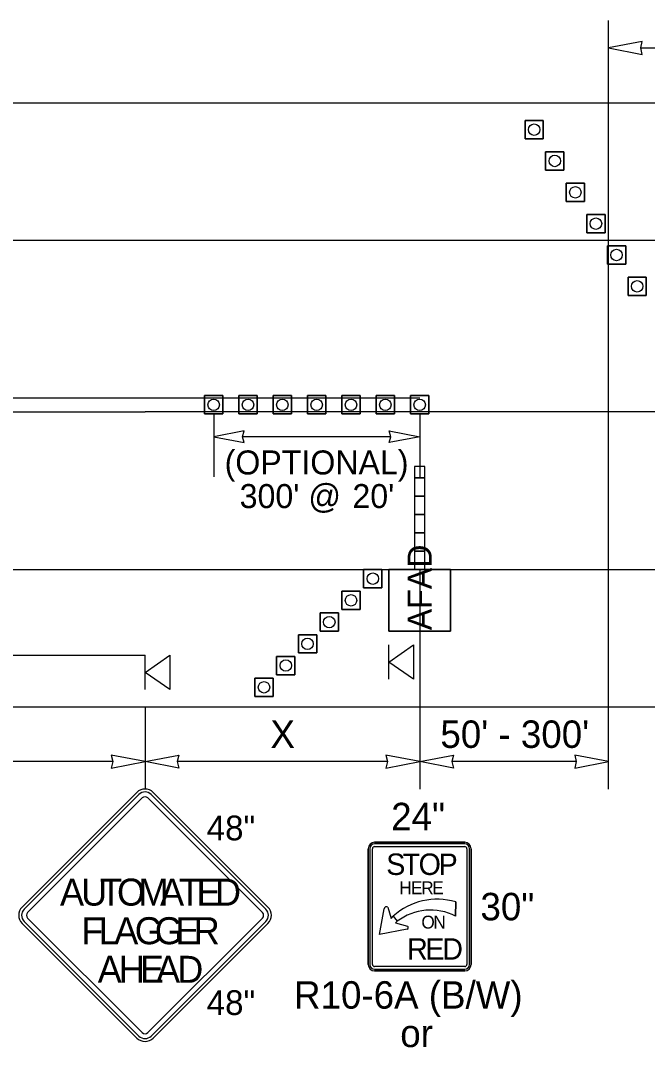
# Model space of a CAD drawing. Extents: x 99999.1 to 100095.7, y 99995 to 100010.7.
# Drawn here: x 100003.114 to 100004.94, y 100004.739 to 100007.732 of the extents above; entities that cross this region are included whole.
import ezdxf

# ---------------------------------------------------------------- set-up
doc = ezdxf.new("R2010")
doc.units = 0
for name, color, linetype in [('RD_ED_ShoulderPavedEdge', 7, 'Continuous'), ('RD_MK_LineDblYellowCenter', 7, 'Continuous'), ('RD_MK_LineEdgeWhite', 7, 'Continuous'), ('RD_MK_LineNoPass', 7, 'Continuous'), ('RD_MK_LineSkipCenter', 7, 'Continuous'), ('TR_SN_ConstructionSigns', 7, 'Continuous'), ('TR_WZ_AFAD', 7, 'Continuous'), ('TR_WZ_PortableSignMountBlk-Org', 7, 'Continuous'), ('TR_WZ_PortableSignMountBlk-Wht', 7, 'Continuous'), ('TR_WZ_TrafficCone', 7, 'Continuous'), ('TR_WZ_WorkZoneDetails', 7, 'Continuous'), ('TR_WZ_WorkZoneTextCurrent', 7, 'Continuous')]:
    doc.layers.add(name, color=color, linetype=linetype)

msp = doc.modelspace()

# ---------------------------------------------------------------- linework, layer by layer
at = {"layer": 'RD_ED_ShoulderPavedEdge'}
for p, q in [((100000.1076, 100007.4923), (100015.6424, 100007.4923)), ((100000.1076, 100005.7323), (100015.6424, 100005.7323))]:
    msp.add_line(p, q, dxfattribs=at)
at = {"layer": 'RD_MK_LineDblYellowCenter'}
for p, q in [((100000.1282, 100006.6323), (100003.4767, 100006.6323)), ((100000.0869, 100006.5923), (100003.4767, 100006.5923))]:
    msp.add_line(p, q, dxfattribs=at)
at = {"layer": 'RD_MK_LineEdgeWhite'}
for p, q in [((100000.1076, 100007.0923), (100015.6424, 100007.0923)), ((100000.1076, 100006.1323), (100015.6424, 100006.1323))]:
    msp.add_line(p, q, dxfattribs=at)
at = {"layer": 'RD_MK_LineNoPass'}
msp.add_line((100003.4767, 100006.6323), (100004.2767, 100006.6323), dxfattribs=at)
at = {"layer": 'RD_MK_LineSkipCenter'}
msp.add_lwpolyline([(100011.15, 100006.5923), (100003.4767, 100006.5923)], dxfattribs=at)
at = {"layer": 'TR_SN_ConstructionSigns'}
for p, q in [((100003.4528, 100005.4824), (100003.1187, 100005.1483)), ((100003.8346, 100005.1483), (100003.5005, 100005.4824)), ((100003.4588, 100005.4765), (100003.1246, 100005.1424)), ((100003.1346, 100005.1324), (100003.4687, 100005.4665)), ((100003.4846, 100005.4665), (100003.8187, 100005.1324)), ((100003.8287, 100005.1424), (100003.4945, 100005.4765)), ((100004.4079, 100005.3373), (100004.1454, 100005.3373)), ((100004.1454, 100005.3373), (100004.4079, 100005.3373)), ((100004.4079, 100005.3373), (100004.1454, 100005.3373)), ((100004.1454, 100005.3373), (100004.4079, 100005.3373)), ((100004.4079, 100005.3326), (100004.1454, 100005.3326)), ((100004.1267, 100005.3186), (100004.1267, 100004.9811)), ((100004.1267, 100004.9811), (100004.1267, 100005.3186)), ((100004.1267, 100005.3186), (100004.1267, 100004.9811)), ((100004.1267, 100004.9811), (100004.1267, 100005.3186)), ((100004.1313, 100005.3186), (100004.1313, 100004.9811)), ((100004.1392, 100004.9811), (100004.1392, 100005.3186)), ((100004.1454, 100005.3248), (100004.4079, 100005.3248)), ((100004.4142, 100005.3186), (100004.4142, 100004.9811)), ((100004.422, 100004.9811), (100004.422, 100005.3186)), ((100004.4267, 100004.9811), (100004.4267, 100005.3186)), ((100004.4267, 100005.3186), (100004.4267, 100004.9811)), ((100004.4267, 100004.9811), (100004.4267, 100005.3186)), ((100004.4267, 100005.3186), (100004.4267, 100004.9811)), ((100004.3816, 100005.1635), (100004.3813, 100005.1216)), ((100004.3813, 100005.1216), (100004.3816, 100005.1635)), ((100004.1595, 100005.0686), (100004.1731, 100005.143)), ((100004.1839, 100005.1479), (100004.1933, 100005.1154)), ((100004.1933, 100005.1154), (100004.1996, 100005.1218)), ((100004.1996, 100005.1218), (100004.2113, 100005.1069)), ((100004.1996, 100005.1218), (100004.2113, 100005.1069)), ((100003.1187, 100005.1006), (100003.4528, 100004.7665)), ((100003.1246, 100005.1066), (100003.4588, 100004.7725)), ((100003.4687, 100004.7824), (100003.1346, 100005.1165)), ((100003.8187, 100005.1165), (100003.4846, 100004.7824)), ((100003.4945, 100004.7725), (100003.8287, 100005.1066)), ((100003.5005, 100004.7665), (100003.8346, 100005.1006)), ((100004.2113, 100005.1069), (100004.2066, 100005.1021)), ((100004.2066, 100005.1021), (100004.2408, 100005.0929)), ((100004.2406, 100005.0837), (100004.1595, 100005.0686)), ((100004.4079, 100004.9748), (100004.1454, 100004.9748)), ((100004.1454, 100004.967), (100004.4079, 100004.967)), ((100004.1454, 100004.9623), (100004.4079, 100004.9623)), ((100004.4079, 100004.9623), (100004.1454, 100004.9623)), ((100004.1454, 100004.9623), (100004.4079, 100004.9623)), ((100004.4079, 100004.9623), (100004.1454, 100004.9623))]:
    msp.add_line(p, q, dxfattribs=at)
for centre, radius, start, end in [((100003.4767, 100005.4586), 0.0338, 45, 135), ((100003.4767, 100005.4586), 0.0253, 45, 135), ((100003.4767, 100005.4586), 0.0113, 45, 135), ((100004.1454, 100005.3186), 0.0187, 90, 180), ((100004.1454, 100005.3186), 0.0187, 90, 180), ((100004.1454, 100005.3186), 0.0187, 90, 180), ((100004.1454, 100005.3186), 0.0187, 90, 180), ((100004.1454, 100005.3186), 0.0141, 90, 180), ((100004.4079, 100005.3186), 0.0187, 0, 90), ((100004.4079, 100005.3186), 0.0187, 0, 90), ((100004.4079, 100005.3186), 0.0187, 0, 90), ((100004.4079, 100005.3186), 0.0187, 0, 90), ((100004.4079, 100005.3186), 0.0141, 0, 90), ((100004.1454, 100005.3186), 0.00625, 90, 180), ((100004.4079, 100005.3186), 0.00625, 0, 90), ((100004.3279, 100004.9804), 0.1909, 73.6434, 132.2131), ((100004.3279, 100004.9804), 0.1909, 73.6434, 132.2131), ((100003.1425, 100005.1245), 0.0338, 135, 225), ((100003.1425, 100005.1245), 0.0253, 135, 225), ((100003.1425, 100005.1245), 0.0113, 135, 225), ((100003.8108, 100005.1245), 0.0113, 315, 45), ((100003.8108, 100005.1245), 0.0253, 315, 45), ((100003.8108, 100005.1245), 0.0338, 315, 45), ((100004.3078, 100004.981), 0.1586, 62.4149, 127.4769), ((100004.3078, 100004.981), 0.1586, 62.4149, 127.4769), ((100004.1454, 100004.9811), 0.0187, 180, 270), ((100004.1454, 100004.9811), 0.0187, 180, 270), ((100004.1454, 100004.9811), 0.0187, 180, 270), ((100004.1454, 100004.9811), 0.0187, 180, 270), ((100004.1454, 100004.9811), 0.0141, 180, 270), ((100004.1454, 100004.9811), 0.00625, 180, 270), ((100004.4079, 100004.9811), 0.0187, 270, 0), ((100004.4079, 100004.9811), 0.0187, 270, 0), ((100004.4079, 100004.9811), 0.0187, 270, 0), ((100004.4079, 100004.9811), 0.0141, 270, 0), ((100004.4079, 100004.9811), 0.00625, 270, 0), ((100004.4079, 100004.9811), 0.0187, 270, 0), ((100003.4767, 100004.7904), 0.0338, 225, 315), ((100003.4767, 100004.7904), 0.0253, 225, 315), ((100003.4767, 100004.7904), 0.0113, 225, 315)]:
    msp.add_arc(centre, radius, start, end, dxfattribs=at)
for centre, major_axis, ratio, start_param, end_param in [((100004.1795, 100005.1431), (-0.00647, -0.00009), 0.989437, 3.962549, 6.283185), ((100004.2384, 100005.0883), (-0.0046, 0.00239), 0.999053, 2.490568, 4.712389)]:
    msp.add_ellipse(centre, major_axis=major_axis, ratio=ratio, start_param=start_param, end_param=end_param, dxfattribs=at)
at = {"layer": 'TR_WZ_AFAD'}
for p, q in [((100004.2916, 100006.399), (100004.2916, 100006.4323)), ((100004.2616, 100006.399), (100004.2616, 100006.3457)), ((100004.2616, 100006.399), (100004.2766, 100006.399)), ((100004.2766, 100006.399), (100004.2916, 100006.399)), ((100004.2916, 100006.3457), (100004.2916, 100006.399)), ((100004.2616, 100006.3457), (100004.2616, 100006.2923)), ((100004.2766, 100006.3457), (100004.2616, 100006.3457)), ((100004.2916, 100006.3457), (100004.2766, 100006.3457)), ((100004.2916, 100006.2923), (100004.2916, 100006.3457)), ((100004.2616, 100006.2923), (100004.2616, 100006.239)), ((100004.2616, 100006.2923), (100004.2766, 100006.2923)), ((100004.2766, 100006.2923), (100004.2916, 100006.2923)), ((100004.2916, 100006.239), (100004.2916, 100006.2923)), ((100004.2766, 100006.239), (100004.2616, 100006.239)), ((100004.2616, 100006.239), (100004.2616, 100006.1857)), ((100004.2916, 100006.239), (100004.2766, 100006.239)), ((100004.2916, 100006.1857), (100004.2916, 100006.239)), ((100004.2616, 100006.1857), (100004.2616, 100006.1323)), ((100004.1866, 100005.9523), (100004.1866, 100006.1323)), ((100004.1866, 100006.1323), (100004.3666, 100006.1323)), ((100004.27, 100006.1323), (100004.1866, 100006.1323)), ((100004.1866, 100006.1323), (100004.1866, 100005.9523)), ((100004.2616, 100006.1323), (100004.27, 100006.1323)), ((100004.27, 100006.1323), (100004.2766, 100006.1323)), ((100004.3666, 100006.1323), (100004.3666, 100005.9523)), ((100004.3666, 100005.9523), (100004.3666, 100006.1323)), ((100004.3666, 100005.9523), (100004.1866, 100005.9523)), ((100004.1866, 100005.9523), (100004.3666, 100005.9523))]:
    msp.add_line(p, q, dxfattribs=at)
for points in [[(100004.2916, 100006.4323), (100004.2616, 100006.4323), (100004.2616, 100006.399)], [(100004.2916, 100006.1323), (100004.2916, 100006.4323), (100004.2616, 100006.4323), (100004.2616, 100006.1323)], [(100004.2916, 100006.399), (100004.2766, 100006.399), (100004.2616, 100006.399)], [(100004.2616, 100006.3457), (100004.2766, 100006.3457), (100004.2916, 100006.3457)], [(100004.2916, 100006.2923), (100004.2766, 100006.2923), (100004.2616, 100006.2923)], [(100004.2616, 100006.239), (100004.2766, 100006.239), (100004.2916, 100006.239)], [(100004.2916, 100006.1857), (100004.2766, 100006.1857), (100004.2616, 100006.1857)], [(100004.2616, 100006.1857), (100004.2766, 100006.1857), (100004.2916, 100006.1857)], [(100004.2766, 100006.1323), (100004.2833, 100006.1323), (100004.2916, 100006.1323), (100004.2916, 100006.1857)], [(100004.3666, 100006.1323), (100004.2833, 100006.1323), (100004.27, 100006.1323)]]:
    msp.add_lwpolyline(points, dxfattribs=at)
at = {"layer": 'TR_WZ_PortableSignMountBlk-Org'}
msp.add_line((100003.4767, 100005.7824), (100003.4767, 100005.8824), dxfattribs=at)
msp.add_lwpolyline([(100003.4767, 100005.8323), (100003.5485, 100005.8824), (100003.5485, 100005.7824)], close=True, dxfattribs=at)
at = {"layer": 'TR_WZ_PortableSignMountBlk-Wht'}
msp.add_line((100004.1867, 100005.8123), (100004.1867, 100005.9123), dxfattribs=at)
msp.add_lwpolyline([(100004.1867, 100005.8622), (100004.2585, 100005.9123), (100004.2585, 100005.8123)], close=True, dxfattribs=at)
at = {"layer": 'TR_WZ_TrafficCone'}
for points in [[(100004.6367, 100007.4411), (100004.5834, 100007.4411), (100004.5834, 100007.3877), (100004.6367, 100007.3877), (100004.6367, 100007.4411)], [(100004.6367, 100007.3877), (100004.5834, 100007.3877), (100004.5834, 100007.4411), (100004.6367, 100007.4411), (100004.6367, 100007.3877)], [(100004.6967, 100007.3497), (100004.6434, 100007.3497), (100004.6434, 100007.2964), (100004.6967, 100007.2964), (100004.6967, 100007.3497)], [(100004.6967, 100007.2964), (100004.6434, 100007.2964), (100004.6434, 100007.3497), (100004.6967, 100007.3497), (100004.6967, 100007.2964)], [(100004.7567, 100007.2584), (100004.7034, 100007.2584), (100004.7034, 100007.2051), (100004.7567, 100007.2051), (100004.7567, 100007.2584)], [(100004.7567, 100007.2051), (100004.7034, 100007.2051), (100004.7034, 100007.2584), (100004.7567, 100007.2584), (100004.7567, 100007.2051)], [(100004.8167, 100007.1671), (100004.7634, 100007.1671), (100004.7634, 100007.1137), (100004.8167, 100007.1137), (100004.8167, 100007.1671)], [(100004.8167, 100007.1137), (100004.7634, 100007.1137), (100004.7634, 100007.1671), (100004.8167, 100007.1671), (100004.8167, 100007.1137)], [(100004.8234, 100007.0757), (100004.8767, 100007.0757), (100004.8767, 100007.0224), (100004.8234, 100007.0224), (100004.8234, 100007.0757)], [(100004.8234, 100007.0224), (100004.8767, 100007.0224), (100004.8767, 100007.0757), (100004.8234, 100007.0757), (100004.8234, 100007.0224)], [(100004.8834, 100006.9844), (100004.9367, 100006.9844), (100004.9367, 100006.9311), (100004.8834, 100006.9311), (100004.8834, 100006.9844)], [(100004.8834, 100006.9311), (100004.9367, 100006.9311), (100004.9367, 100006.9844), (100004.8834, 100006.9844), (100004.8834, 100006.9311)], [(100003.7033, 100006.639), (100003.65, 100006.639), (100003.65, 100006.5857), (100003.7033, 100006.5857), (100003.7033, 100006.639)], [(100003.7033, 100006.5857), (100003.65, 100006.5857), (100003.65, 100006.639), (100003.7033, 100006.639), (100003.7033, 100006.5857)], [(100003.8033, 100006.639), (100003.75, 100006.639), (100003.75, 100006.5857), (100003.8033, 100006.5857), (100003.8033, 100006.639)], [(100003.8033, 100006.5857), (100003.75, 100006.5857), (100003.75, 100006.639), (100003.8033, 100006.639), (100003.8033, 100006.5857)], [(100003.9033, 100006.639), (100003.85, 100006.639), (100003.85, 100006.5857), (100003.9033, 100006.5857), (100003.9033, 100006.639)], [(100003.9033, 100006.5857), (100003.85, 100006.5857), (100003.85, 100006.639), (100003.9033, 100006.639), (100003.9033, 100006.5857)], [(100004.0033, 100006.639), (100003.95, 100006.639), (100003.95, 100006.5857), (100004.0033, 100006.5857), (100004.0033, 100006.639)], [(100004.0033, 100006.5857), (100003.95, 100006.5857), (100003.95, 100006.639), (100004.0033, 100006.639), (100004.0033, 100006.5857)], [(100004.1033, 100006.639), (100004.05, 100006.639), (100004.05, 100006.5857), (100004.1033, 100006.5857), (100004.1033, 100006.639)], [(100004.1033, 100006.5857), (100004.05, 100006.5857), (100004.05, 100006.639), (100004.1033, 100006.639), (100004.1033, 100006.5857)], [(100004.2033, 100006.639), (100004.15, 100006.639), (100004.15, 100006.5857), (100004.2033, 100006.5857), (100004.2033, 100006.639)], [(100004.2033, 100006.5857), (100004.15, 100006.5857), (100004.15, 100006.639), (100004.2033, 100006.639), (100004.2033, 100006.5857)], [(100004.3033, 100006.639), (100004.25, 100006.639), (100004.25, 100006.5857), (100004.3033, 100006.5857), (100004.3033, 100006.639)], [(100004.3033, 100006.5857), (100004.25, 100006.5857), (100004.25, 100006.639), (100004.3033, 100006.639), (100004.3033, 100006.5857)], [(100004.1133, 100006.1323), (100004.1667, 100006.1323), (100004.1667, 100006.079), (100004.1133, 100006.079), (100004.1133, 100006.1323)], [(100004.1133, 100006.079), (100004.1667, 100006.079), (100004.1667, 100006.1323), (100004.1133, 100006.1323), (100004.1133, 100006.079)], [(100004.05, 100006.069), (100004.1033, 100006.069), (100004.1033, 100006.0157), (100004.05, 100006.0157), (100004.05, 100006.069)], [(100004.05, 100006.0157), (100004.1033, 100006.0157), (100004.1033, 100006.069), (100004.05, 100006.069), (100004.05, 100006.0157)], [(100003.9867, 100006.0057), (100004.04, 100006.0057), (100004.04, 100005.9523), (100003.9867, 100005.9523), (100003.9867, 100006.0057)], [(100003.9867, 100005.9523), (100004.04, 100005.9523), (100004.04, 100006.0057), (100003.9867, 100006.0057), (100003.9867, 100005.9523)], [(100003.9767, 100005.9423), (100003.9233, 100005.9423), (100003.9233, 100005.889), (100003.9767, 100005.889), (100003.9767, 100005.9423)], [(100003.9767, 100005.889), (100003.9233, 100005.889), (100003.9233, 100005.9423), (100003.9767, 100005.9423), (100003.9767, 100005.889)], [(100003.9133, 100005.879), (100003.86, 100005.879), (100003.86, 100005.8257), (100003.9133, 100005.8257), (100003.9133, 100005.879)], [(100003.9133, 100005.8257), (100003.86, 100005.8257), (100003.86, 100005.879), (100003.9133, 100005.879), (100003.9133, 100005.8257)], [(100003.85, 100005.8157), (100003.7967, 100005.8157), (100003.7967, 100005.7623), (100003.85, 100005.7623), (100003.85, 100005.8157)], [(100003.85, 100005.7623), (100003.7967, 100005.7623), (100003.7967, 100005.8157), (100003.85, 100005.8157), (100003.85, 100005.7623)]]:
    msp.add_lwpolyline(points, dxfattribs=at)
for centre in [(100004.61, 100007.4144), (100004.67, 100007.3231), (100004.73, 100007.2317), (100004.79, 100007.1404), (100004.85, 100007.0491), (100004.91, 100006.9577), (100003.6767, 100006.6123), (100003.7767, 100006.6123), (100003.8767, 100006.6123), (100003.9767, 100006.6123), (100004.0767, 100006.6123), (100004.1767, 100006.6123), (100004.2767, 100006.6123), (100004.14, 100006.1057), (100004.0767, 100006.0423), (100004.0133, 100005.979), (100003.95, 100005.9157), (100003.8867, 100005.8523), (100003.8233, 100005.789)]:
    msp.add_circle(centre, 0.0167, dxfattribs=at)
at = {"layer": 'TR_WZ_WorkZoneDetails'}
for p, q in [((100004.8267, 100005.4923), (100004.8267, 100007.7323)), ((100004.9204, 100007.6523), (100005.0563, 100007.6523)), ((100003.6767, 100006.5857), (100003.6767, 100006.4023)), ((100004.2767, 100006.5857), (100004.2767, 100006.4023)), ((100004.1923, 100006.5193), (100003.761, 100006.5193)), ((100004.2767, 100006.1323), (100004.2767, 100005.4923)), ((100001.0767, 100005.8824), (100003.4767, 100005.8824)), ((100003.4767, 100005.7323), (100003.4767, 100005.4923)), ((100003.3829, 100005.5723), (100002.7704, 100005.5723)), ((100004.1829, 100005.5723), (100003.5704, 100005.5723)), ((100004.7329, 100005.5723), (100004.3704, 100005.5723))]:
    msp.add_line(p, q, dxfattribs=at)
for points in [[(100004.8267, 100007.6523), (100004.9249, 100007.6331), (100004.9204, 100007.6523), (100004.9249, 100007.6716)], [(100003.6767, 100006.5193), (100003.7651, 100006.502), (100003.761, 100006.5193), (100003.7651, 100006.5367)], [(100004.2767, 100006.5193), (100004.1882, 100006.502), (100004.1923, 100006.5193), (100004.1882, 100006.5367)], [(100003.4767, 100005.5723), (100003.3784, 100005.5916), (100003.3829, 100005.5723), (100003.3784, 100005.5531)], [(100003.4767, 100005.5723), (100003.5749, 100005.5916), (100003.5704, 100005.5723), (100003.5749, 100005.5531)], [(100004.2767, 100005.5723), (100004.1784, 100005.5916), (100004.1829, 100005.5723), (100004.1784, 100005.5531)], [(100004.2767, 100005.5723), (100004.3749, 100005.5916), (100004.3704, 100005.5723), (100004.3749, 100005.5531)], [(100004.8267, 100005.5723), (100004.7284, 100005.5916), (100004.7329, 100005.5723), (100004.7284, 100005.5531)]]:
    msp.add_lwpolyline(points, close=True, dxfattribs=at)

# ---------------------------------------------------------------- texts
at = {"layer": 'TR_SN_ConstructionSigns'}
for s, height, p in [('24"', 0.08, (100004.1936, 100005.3723)), ('48"', 0.072, (100003.6564, 100005.343)), ('30"', 0.08, (100004.4536, 100005.1098)), ('R10-6A (B/W)', 0.08, (100003.9107, 100004.8523)), ('48"', 0.072, (100003.6564, 100004.8339)), ('or', 0.08, (100004.2201, 100004.7403))]:
    msp.add_text(s, height=height, rotation=360, dxfattribs=at).set_placement(p)
for s, height, p in [('S', 0.0625, (100004.1792, 100005.242)), ('T', 0.0625, (100004.2267, 100005.242)), ('O', 0.0625, (100004.2735, 100005.242)), ('P', 0.0625, (100004.3317, 100005.242)), ('A', 0.0787, (100003.229, 100005.1526)), ('U', 0.0787, (100003.2904, 100005.1526)), ('T', 0.0787, (100003.3455, 100005.1526)), ('O', 0.0787, (100003.3951, 100005.1526)), ('M', 0.0787, (100003.4574, 100005.1526)), ('A', 0.0787, (100003.5204, 100005.1526)), ('T', 0.0787, (100003.5755, 100005.1526)), ('E', 0.0787, (100003.6267, 100005.1526)), ('D', 0.0787, (100003.6802, 100005.1526)), ('H', 0.0375, (100004.217, 100005.1858)), ('E', 0.0375, (100004.2515, 100005.1858)), ('R', 0.0375, (100004.2812, 100005.1858)), ('E', 0.0375, (100004.313, 100005.1858)), ('F', 0.0787, (100003.2908, 100005.0401)), ('L', 0.0787, (100003.342, 100005.0401)), ('A', 0.0787, (100003.3869, 100005.0401)), ('G', 0.0787, (100003.4467, 100005.0401)), ('G', 0.0787, (100003.505, 100005.0401)), ('E', 0.0787, (100003.5649, 100005.0401)), ('R', 0.0787, (100003.6184, 100005.0401)), ('O', 0.0375, (100004.2815, 100005.0858)), ('N', 0.0375, (100004.3164, 100005.0858)), ('R', 0.0625, (100004.2399, 100004.9951)), ('E', 0.0625, (100004.293, 100004.9951)), ('D', 0.0625, (100004.3424, 100004.9951)), ('A', 0.0787, (100003.3388, 100004.9276)), ('H', 0.0787, (100003.4003, 100004.9276)), ('E', 0.0787, (100003.4617, 100004.9276)), ('A', 0.0787, (100003.5089, 100004.9276)), ('D', 0.0787, (100003.5704, 100004.9276))]:
    msp.add_text(s, height=height, dxfattribs=at).set_placement(p)
at = {"layer": 'TR_WZ_AFAD'}
msp.add_text('AFAD', height=0.07, rotation=90, dxfattribs=at).set_placement((100004.3116, 100005.9553))
at = {"layer": 'TR_WZ_WorkZoneTextCurrent'}
for s, p in [('(OPTIONAL)', (100003.7085, 100006.4093)), ("300' @", (100003.7523, 100006.3113)), ("20'", (100004.0807, 100006.3113))]:
    msp.add_text(s, height=0.07, dxfattribs=at).set_placement(p)
for s, p in [('X', (100003.8419, 100005.6123)), ("50' - 300'", (100004.3369, 100005.6123))]:
    msp.add_text(s, height=0.08, rotation=360, dxfattribs=at).set_placement(p)

doc.saveas('drawing.dxf')
